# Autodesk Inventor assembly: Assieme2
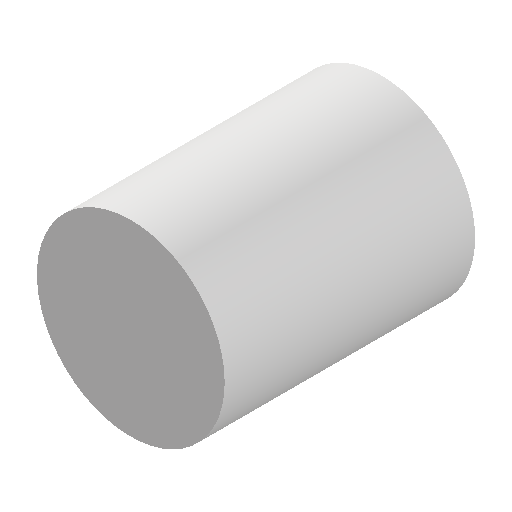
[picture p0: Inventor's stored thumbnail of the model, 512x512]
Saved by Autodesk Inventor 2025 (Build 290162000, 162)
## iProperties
Created: 2025-10
Part Number: Assieme2
Document SubType Name: Assembly
Designer: Ryzen5700u
Author: Ryzen5700u
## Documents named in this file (2)
- C:\Users\Ryzen5700u\Desktop\trasm. croce di malta\Assieme2.iam
- C:\Users\Ryzen5700u\Desktop\trasm. croce di malta\Parte10.ipt
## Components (1 placed, 1 different names)
1. Parte10:1
